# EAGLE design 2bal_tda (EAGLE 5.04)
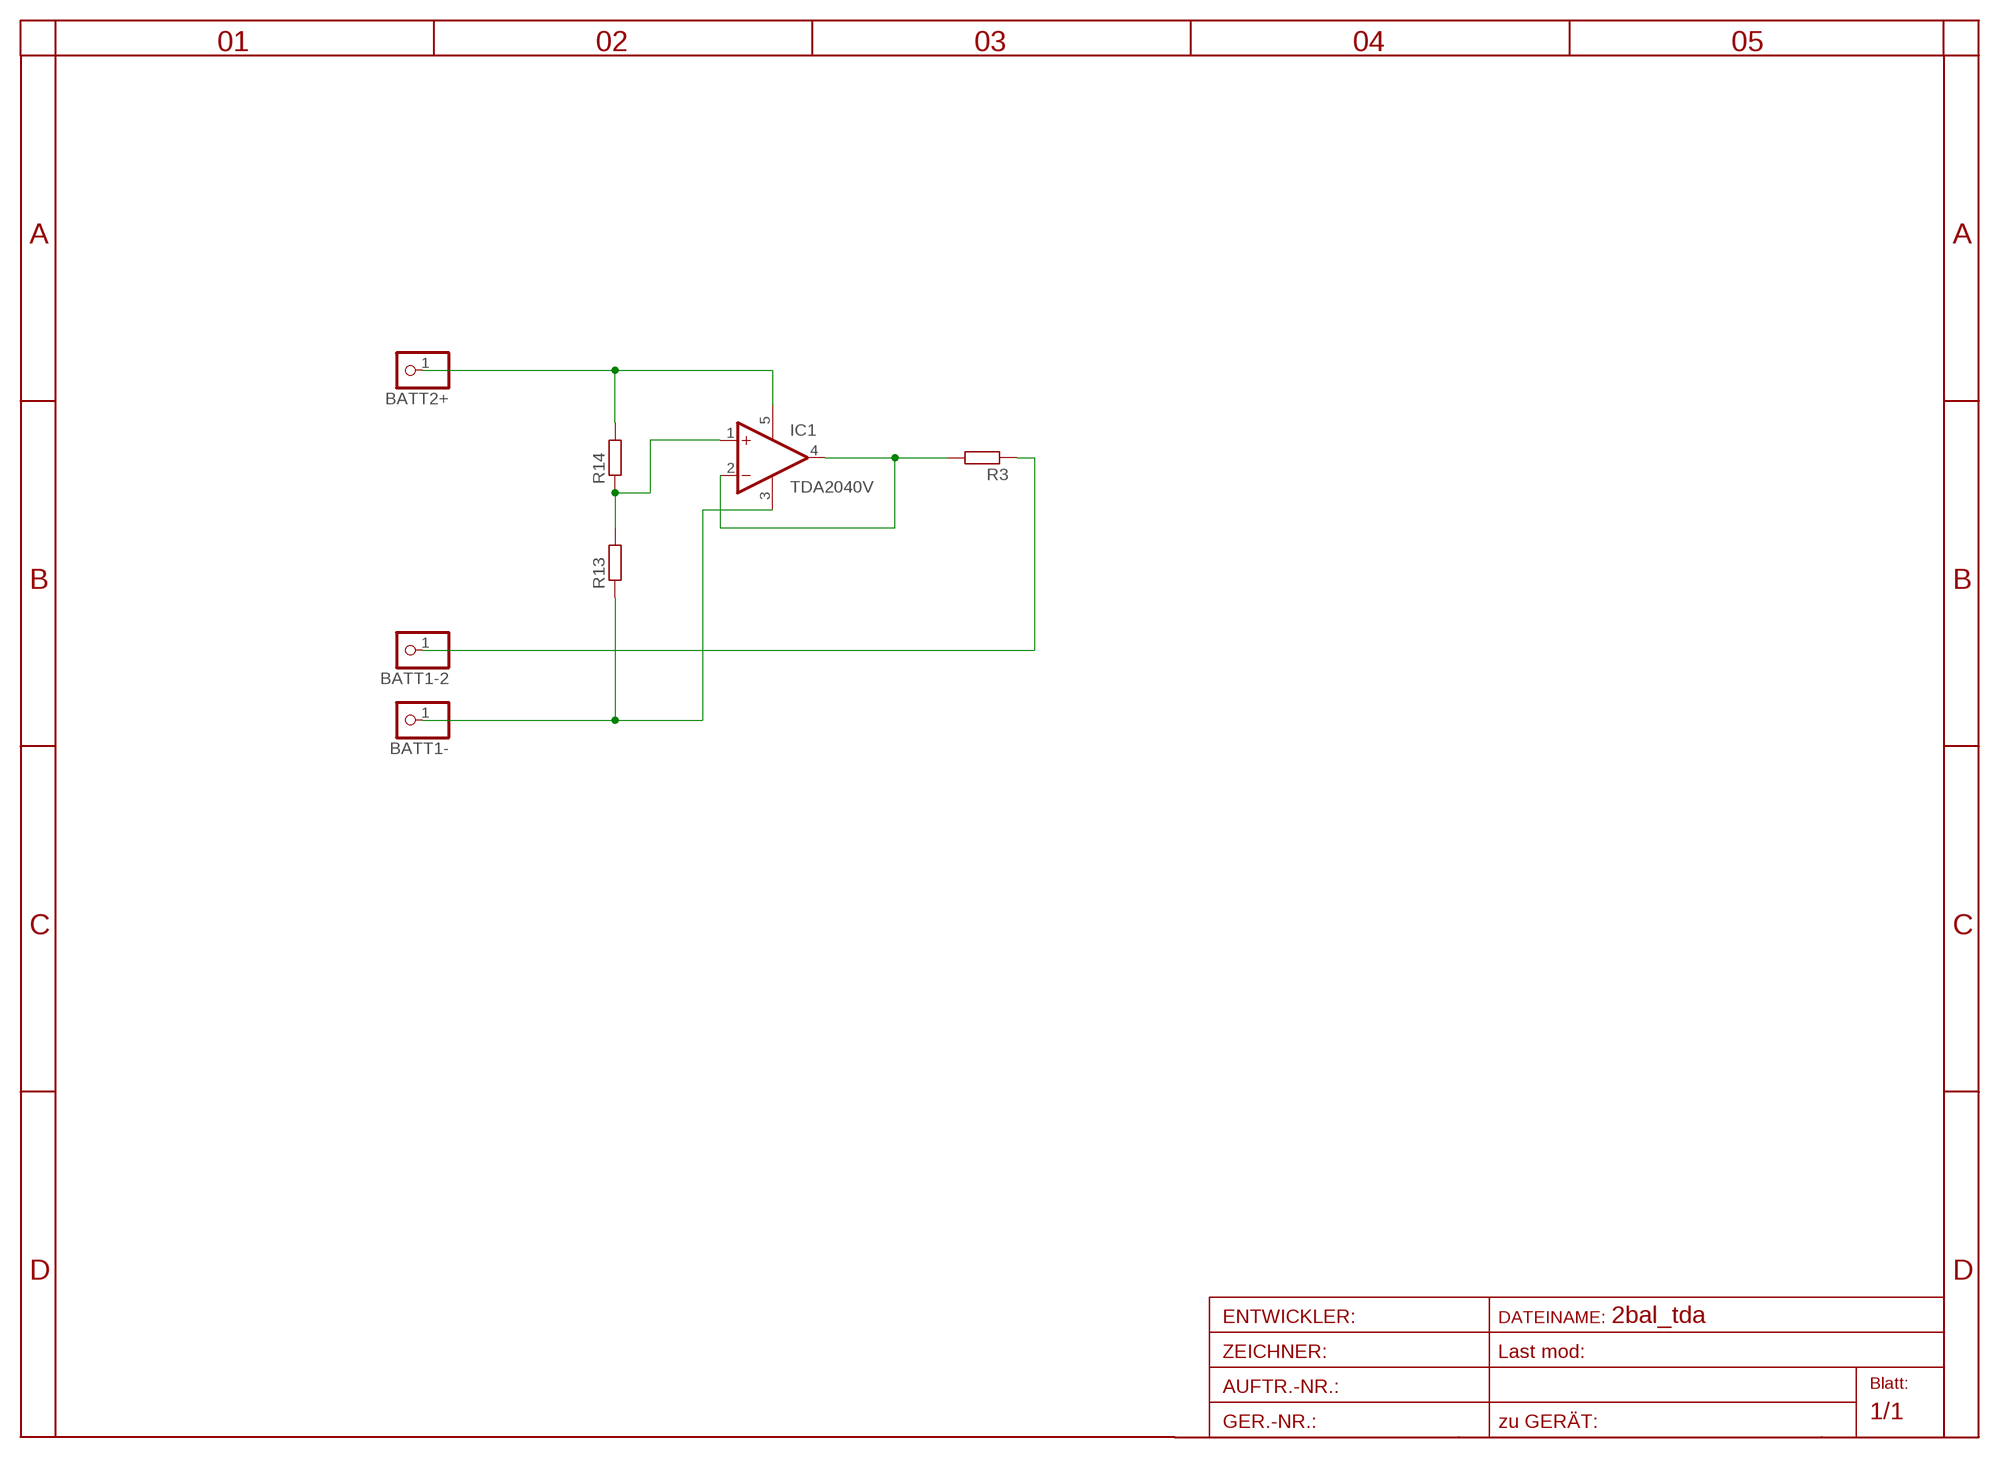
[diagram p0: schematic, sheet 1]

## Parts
BATT1-  PINHD-1X1  [1X01]
BATT1-2  PINHD-1X1  [1X01]
BATT2+  PINHD-1X1  [1X01]
IC1  TDA2040V  [CB360]
R3  R-EU_0309/10  [0309/10]
R13  R-EU_0204/5  [0204/5]
R14  R-EU_0204/5  [0204/5]

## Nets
B1: BATT1-2.1 R3.1
N$1: BATT1-.1 IC1.3(V-) R13.1
N$2: IC1.2(-IN) IC1.4(OUT) R3.2
N$3: BATT2+.1 IC1.5(V+) R14.2
N$28: IC1.1(+IN) R13.2 R14.1

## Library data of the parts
BATT1- BATT1-2 BATT2+ = pinhead:PINHD-1X1: PIN HEADER
IC1 = linear:TDA2040: Power OP AMP
R3 R13 R14 = rcl-2:R-EU_: RESISTOR, European symbol

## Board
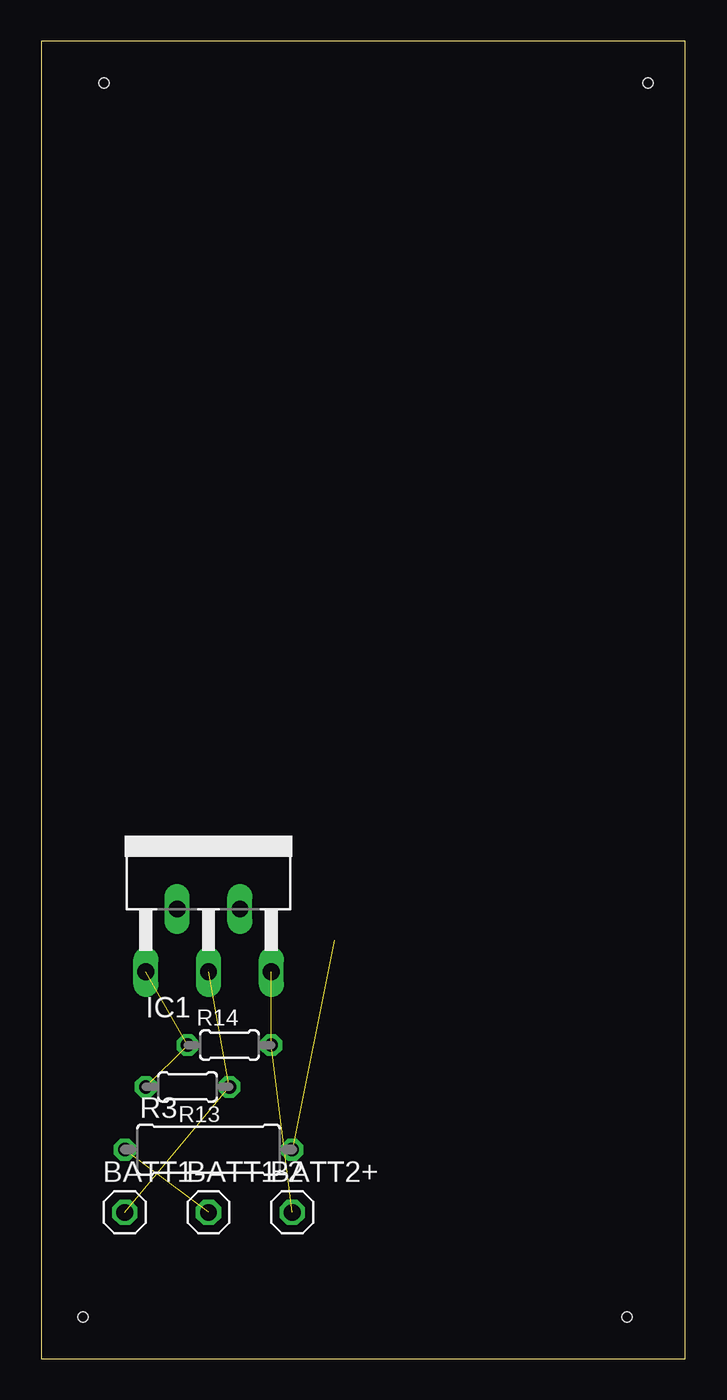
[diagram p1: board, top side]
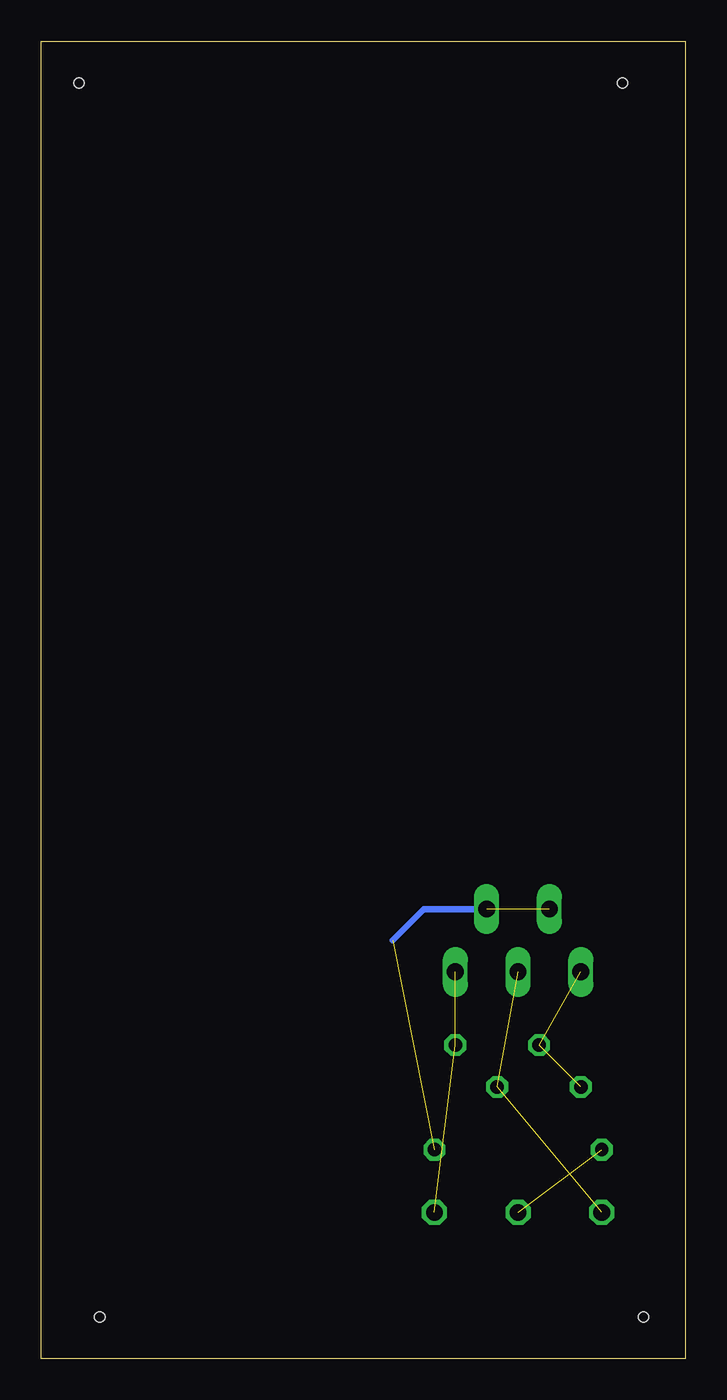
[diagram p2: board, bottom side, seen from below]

Size 39.12 x 80 mm. Coordinates in mm from the lower left corner, seen from the top.
Outline: 0,0 39.12,0 39.12,80 0,80 0,0
Copper layers (1*16): Top 0.035mm / dielectric 1.5mm / Bottom 0.035mm
Design rules "default": minimum track width 10mil, minimum drill 24mil, track to track 8mil, track to pad 8mil, pad to pad 8mil, via to via 8mil, smd to smd 8mil, copper to edge 40mil, drill to drill 8mil, minimum pad ring 10mil, minimum via ring 8mil, stop-mask expansion 4mil, vias tented up to drill 0mil, thermal gap 10mil
Holes 0.6 mm at 2.54,2.54 35.56,2.54 36.83,77.47 3.81,77.47

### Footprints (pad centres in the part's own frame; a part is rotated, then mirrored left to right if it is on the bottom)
1X01 = drill 1.016 octagon: 1 0,0
CB360 = drill 1.016 long: 1 -3.81,-8.255; 2 -1.905,-4.445; 3 0,-8.255; 4 1.905,-4.445; 5 3.81,-8.255
0309/10 = drill 0.813 octagon: 1 -5.08,0; 2 5.08,0
0204/5 = drill 0.813 octagon: 1 -2.54,0; 2 2.54,0

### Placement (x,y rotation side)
BATT1-  5.08,8.89 0 top
BATT1-2  10.16,8.89 0 top
BATT2+  15.24,8.89 0 top
IC1  10.16,31.75 0 top
R3  10.16,12.7 0 top
R13  8.89,16.51 180 top
R14  11.43,19.05 0 top

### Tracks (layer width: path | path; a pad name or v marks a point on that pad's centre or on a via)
B1  (1 unrouted)
N$1  (2 unrouted)
N$2  (2 unrouted)
  Bottom 0.406: IC1.4 15.88,27.3 17.78,25.4
N$3  (2 unrouted)
N$28  (2 unrouted)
